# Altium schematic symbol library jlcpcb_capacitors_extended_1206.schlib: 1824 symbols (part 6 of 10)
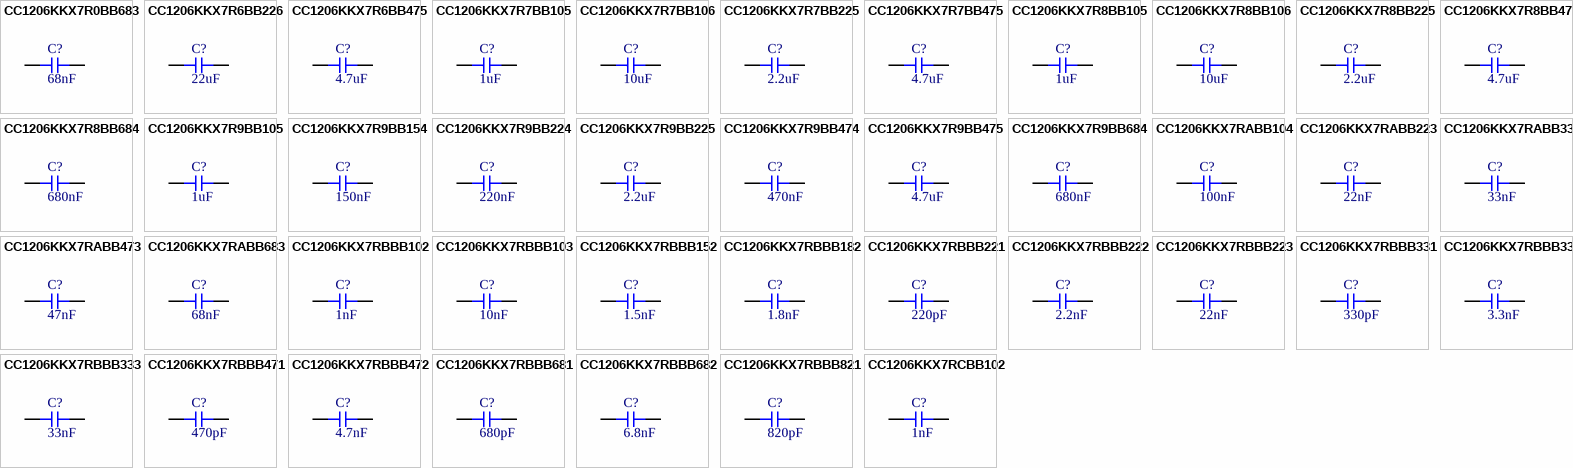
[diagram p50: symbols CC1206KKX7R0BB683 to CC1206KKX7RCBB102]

## CC1206KKX7RBBB223
designator C?  Capacitance: 22nF  (hidden comment: *)
Capacitor, Ceramic (MLCC), 22nF, ±10%, 500V, X7R, ±10%, SMD 1206; Manufacturer: YAGEO; Manufacturer Part Number: CC1206KKX7RBBB223
footprint CAP-1206 (1206 (3216M) Capacitor)
pins: 1, 2

## CC1206KKX7RBBB331
designator C?  Capacitance: 330pF  (hidden comment: *)
Capacitor, Ceramic (MLCC), 330pF, ±10%, 500V, X7R, ±10%, SMD 1206; Manufacturer: YAGEO; Manufacturer Part Number: CC1206KKX7RBBB331
footprint CAP-1206 (1206 (3216M) Capacitor)
pins: 1, 2

## CC1206KKX7RBBB332
designator C?  Capacitance: 3.3nF  (hidden comment: *)
Capacitor, Ceramic (MLCC), 3.3nF, ±10%, 500V, X7R, ±10%, SMD 1206; Manufacturer: YAGEO; Manufacturer Part Number: CC1206KKX7RBBB332
footprint CAP-1206 (1206 (3216M) Capacitor)
pins: 1, 2

## CC1206KKX7RBBB333
designator C?  Capacitance: 33nF  (hidden comment: *)
Capacitor, Ceramic (MLCC), 33nF, ±10%, 500V, X7R, ±10%, SMD 1206; Manufacturer: YAGEO; Manufacturer Part Number: CC1206KKX7RBBB333
footprint CAP-1206 (1206 (3216M) Capacitor)
pins: 1, 2

## CC1206KKX7RBBB471
designator C?  Capacitance: 470pF  (hidden comment: *)
Capacitor, Ceramic (MLCC), 470pF, ±10%, 500V, X7R, ±10%, SMD 1206; Manufacturer: YAGEO; Manufacturer Part Number: CC1206KKX7RBBB471
footprint CAP-1206 (1206 (3216M) Capacitor)
pins: 1, 2

## CC1206KKX7RBBB472
designator C?  Capacitance: 4.7nF  (hidden comment: *)
Capacitor, Ceramic (MLCC), 4.7nF, ±10%, 500V, X7R, ±10%, SMD 1206; Manufacturer: YAGEO; Manufacturer Part Number: CC1206KKX7RBBB472
footprint CAP-1206 (1206 (3216M) Capacitor)
pins: 1, 2

## CC1206KKX7RBBB681
designator C?  Capacitance: 680pF  (hidden comment: *)
Capacitor, Ceramic (MLCC), 680pF, ±10%, 500V, X7R, ±10%, SMD 1206; Manufacturer: YAGEO; Manufacturer Part Number: CC1206KKX7RBBB681
footprint CAP-1206 (1206 (3216M) Capacitor)
pins: 1, 2

## CC1206KKX7RBBB682
designator C?  Capacitance: 6.8nF  (hidden comment: *)
Capacitor, Ceramic (MLCC), 6.8nF, ±10%, 500V, X7R, ±10%, SMD 1206; Manufacturer: YAGEO; Manufacturer Part Number: CC1206KKX7RBBB682
footprint CAP-1206 (1206 (3216M) Capacitor)
pins: 1, 2

## CC1206KKX7RBBB821
designator C?  Capacitance: 820pF  (hidden comment: *)
Capacitor, Ceramic (MLCC), 820pF, ±10%, 500V, X7R, ±10%, SMD 1206; Manufacturer: YAGEO; Manufacturer Part Number: CC1206KKX7RBBB821
footprint CAP-1206 (1206 (3216M) Capacitor)
pins: 1, 2

## CC1206KKX7RCBB102
designator C?  Capacitance: 1nF  (hidden comment: *)
Capacitor, Ceramic (MLCC), 1nF, ±10%, 1kV, X7R, ±10%, SMD 1206; Manufacturer: YAGEO; Manufacturer Part Number: CC1206KKX7RCBB102
footprint CAP-1206 (1206 (3216M) Capacitor)
pins: 1, 2

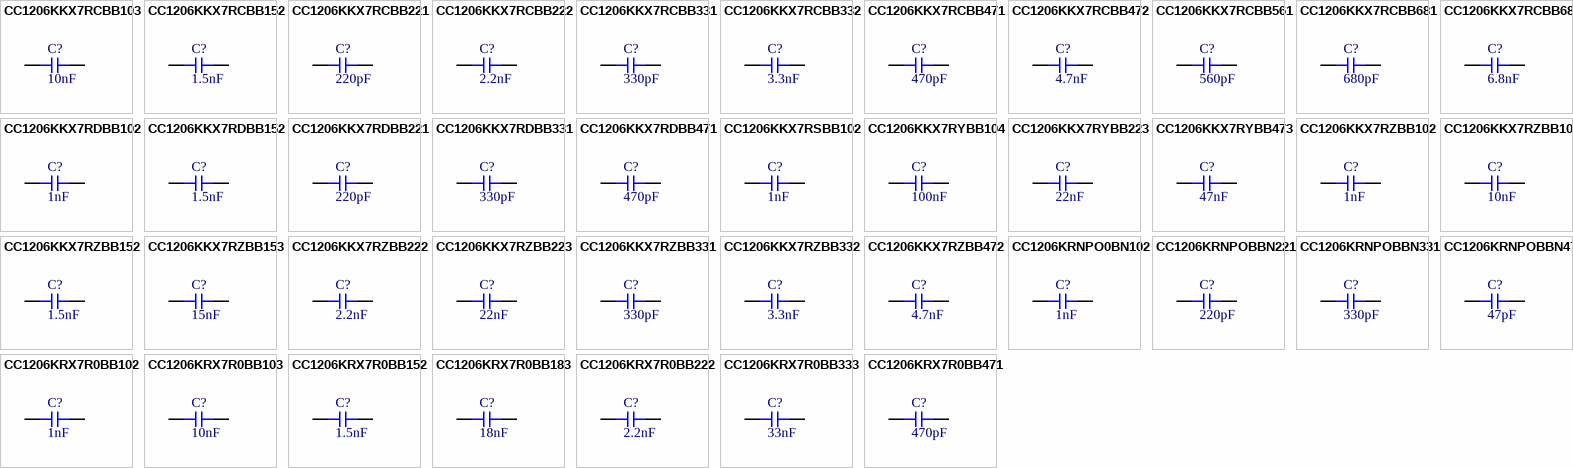
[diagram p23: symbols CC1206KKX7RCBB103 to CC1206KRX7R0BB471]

## CC1206KKX7RCBB103
designator C?  Capacitance: 10nF  (hidden comment: *)
Capacitor, Ceramic (MLCC), 10nF, ±10%, 1kV, X7R, ±10%, SMD 1206; Manufacturer: YAGEO; Manufacturer Part Number: CC1206KKX7RCBB103
footprint CAP-1206 (1206 (3216M) Capacitor)
pins: 1, 2

## CC1206KKX7RCBB152
designator C?  Capacitance: 1.5nF  (hidden comment: *)
Capacitor, Ceramic (MLCC), 1.5nF, ±10%, 1kV, X7R, ±10%, SMD 1206; Manufacturer: YAGEO; Manufacturer Part Number: CC1206KKX7RCBB152
footprint CAP-1206 (1206 (3216M) Capacitor)
pins: 1, 2

## CC1206KKX7RCBB221
designator C?  Capacitance: 220pF  (hidden comment: *)
Capacitor, Ceramic (MLCC), 220pF, ±10%, 1kV, X7R, ±10%, SMD 1206; Manufacturer: YAGEO; Manufacturer Part Number: CC1206KKX7RCBB221
footprint CAP-1206 (1206 (3216M) Capacitor)
pins: 1, 2

## CC1206KKX7RCBB222
designator C?  Capacitance: 2.2nF  (hidden comment: *)
Capacitor, Ceramic (MLCC), 2.2nF, ±10%, 1kV, X7R, ±10%, SMD 1206; Manufacturer: YAGEO; Manufacturer Part Number: CC1206KKX7RCBB222
footprint CAP-1206 (1206 (3216M) Capacitor)
pins: 1, 2

## CC1206KKX7RCBB331
designator C?  Capacitance: 330pF  (hidden comment: *)
Capacitor, Ceramic (MLCC), 330pF, ±10%, 1kV, X7R, ±10%, SMD 1206; Manufacturer: YAGEO; Manufacturer Part Number: CC1206KKX7RCBB331
footprint CAP-1206 (1206 (3216M) Capacitor)
pins: 1, 2

## CC1206KKX7RCBB332
designator C?  Capacitance: 3.3nF  (hidden comment: *)
Capacitor, Ceramic (MLCC), 3.3nF, ±10%, 1kV, X7R, ±10%, SMD 1206; Manufacturer: YAGEO; Manufacturer Part Number: CC1206KKX7RCBB332
footprint CAP-1206 (1206 (3216M) Capacitor)
pins: 1, 2

## CC1206KKX7RCBB471
designator C?  Capacitance: 470pF  (hidden comment: *)
Capacitor, Ceramic (MLCC), 470pF, ±10%, 1kV, X7R, ±10%, SMD 1206; Manufacturer: YAGEO; Manufacturer Part Number: CC1206KKX7RCBB471
footprint CAP-1206 (1206 (3216M) Capacitor)
pins: 1, 2

## CC1206KKX7RCBB472
designator C?  Capacitance: 4.7nF  (hidden comment: *)
Capacitor, Ceramic (MLCC), 4.7nF, ±10%, 1kV, X7R, ±10%, SMD 1206; Manufacturer: YAGEO; Manufacturer Part Number: CC1206KKX7RCBB472
footprint CAP-1206 (1206 (3216M) Capacitor)
pins: 1, 2

## CC1206KKX7RCBB561
designator C?  Capacitance: 560pF  (hidden comment: *)
Capacitor, Ceramic (MLCC), 560pF, ±10%, 1kV, X7R, ±10%, SMD 1206; Manufacturer: YAGEO; Manufacturer Part Number: CC1206KKX7RCBB561
footprint CAP-1206 (1206 (3216M) Capacitor)
pins: 1, 2

## CC1206KKX7RCBB681
designator C?  Capacitance: 680pF  (hidden comment: *)
Capacitor, Ceramic (MLCC), 680pF, ±10%, 1kV, X7R, ±10%, SMD 1206; Manufacturer: YAGEO; Manufacturer Part Number: CC1206KKX7RCBB681
footprint CAP-1206 (1206 (3216M) Capacitor)
pins: 1, 2

## CC1206KKX7RCBB682
designator C?  Capacitance: 6.8nF  (hidden comment: *)
Capacitor, Ceramic (MLCC), 6.8nF, ±10%, 1kV, X7R, ±10%, SMD 1206; Manufacturer: YAGEO; Manufacturer Part Number: CC1206KKX7RCBB682
footprint CAP-1206 (1206 (3216M) Capacitor)
pins: 1, 2

## CC1206KKX7RDBB102
designator C?  Capacitance: 1nF  (hidden comment: *)
Capacitor, Ceramic (MLCC), 1nF, ±10%, 2kV, X7R, ±10%, SMD 1206; Manufacturer: YAGEO; Manufacturer Part Number: CC1206KKX7RDBB102
footprint CAP-1206 (1206 (3216M) Capacitor)
pins: 1, 2

## CC1206KKX7RDBB152
designator C?  Capacitance: 1.5nF  (hidden comment: *)
Capacitor, Ceramic (MLCC), 1.5nF, ±10%, 2kV, X7R, ±10%, SMD 1206; Manufacturer: YAGEO; Manufacturer Part Number: CC1206KKX7RDBB152
footprint CAP-1206 (1206 (3216M) Capacitor)
pins: 1, 2

## CC1206KKX7RDBB221
designator C?  Capacitance: 220pF  (hidden comment: *)
Capacitor, Ceramic (MLCC), 220pF, ±10%, 2kV, X7R, ±10%, SMD 1206; Manufacturer: YAGEO; Manufacturer Part Number: CC1206KKX7RDBB221
footprint CAP-1206 (1206 (3216M) Capacitor)
pins: 1, 2

## CC1206KKX7RDBB331
designator C?  Capacitance: 330pF  (hidden comment: *)
Capacitor, Ceramic (MLCC), 330pF, ±10%, 2kV, X7R, ±10%, SMD 1206; Manufacturer: YAGEO; Manufacturer Part Number: CC1206KKX7RDBB331
footprint CAP-1206 (1206 (3216M) Capacitor)
pins: 1, 2

## CC1206KKX7RDBB471
designator C?  Capacitance: 470pF  (hidden comment: *)
Capacitor, Ceramic (MLCC), 470pF, ±10%, 2kV, X7R, ±10%, SMD 1206; Manufacturer: YAGEO; Manufacturer Part Number: CC1206KKX7RDBB471
footprint CAP-1206 (1206 (3216M) Capacitor)
pins: 1, 2

## CC1206KKX7RSBB102
designator C?  Capacitance: 1nF  (hidden comment: *)
Capacitor, Ceramic (MLCC), 1nF, ±10%, 2.5kV, X7R, ±10%, SMD 1206; Manufacturer: YAGEO; Manufacturer Part Number: CC1206KKX7RSBB102
footprint CAP-1206 (1206 (3216M) Capacitor)
pins: 1, 2

## CC1206KKX7RYBB104
designator C?  Capacitance: 100nF  (hidden comment: *)
Capacitor, Ceramic (MLCC), 100nF, ±10%, 250V, X7R, ±10%, SMD 1206; Manufacturer: YAGEO; Manufacturer Part Number: CC1206KKX7RYBB104
footprint CAP-1206 (1206 (3216M) Capacitor)
pins: 1, 2

## CC1206KKX7RYBB223
designator C?  Capacitance: 22nF  (hidden comment: *)
Capacitor, Ceramic (MLCC), 22nF, ±10%, 250V, X7R, ±10%, SMD 1206; Manufacturer: YAGEO; Manufacturer Part Number: CC1206KKX7RYBB223
footprint CAP-1206 (1206 (3216M) Capacitor)
pins: 1, 2

## CC1206KKX7RYBB473
designator C?  Capacitance: 47nF  (hidden comment: *)
Capacitor, Ceramic (MLCC), 47nF, ±10%, 250V, X7R, ±10%, SMD 1206; Manufacturer: YAGEO; Manufacturer Part Number: CC1206KKX7RYBB473
footprint CAP-1206 (1206 (3216M) Capacitor)
pins: 1, 2

## CC1206KKX7RZBB102
designator C?  Capacitance: 1nF  (hidden comment: *)
Capacitor, Ceramic (MLCC), 1nF, ±10%, 630V, X7R, ±10%, SMD 1206; Manufacturer: YAGEO; Manufacturer Part Number: CC1206KKX7RZBB102
footprint CAP-1206 (1206 (3216M) Capacitor)
pins: 1, 2

## CC1206KKX7RZBB103
designator C?  Capacitance: 10nF  (hidden comment: *)
Capacitor, Ceramic (MLCC), 10nF, ±10%, 630V, X7R, ±10%, SMD 1206; Manufacturer: YAGEO; Manufacturer Part Number: CC1206KKX7RZBB103
footprint CAP-1206 (1206 (3216M) Capacitor)
pins: 1, 2

## CC1206KKX7RZBB152
designator C?  Capacitance: 1.5nF  (hidden comment: *)
Capacitor, Ceramic (MLCC), 1.5nF, ±10%, 630V, X7R, ±10%, SMD 1206; Manufacturer: YAGEO; Manufacturer Part Number: CC1206KKX7RZBB152
footprint CAP-1206 (1206 (3216M) Capacitor)
pins: 1, 2

## CC1206KKX7RZBB153
designator C?  Capacitance: 15nF  (hidden comment: *)
Capacitor, Ceramic (MLCC), 15nF, ±10%, 630V, X7R, ±10%, SMD 1206; Manufacturer: YAGEO; Manufacturer Part Number: CC1206KKX7RZBB153
footprint CAP-1206 (1206 (3216M) Capacitor)
pins: 1, 2

## CC1206KKX7RZBB222
designator C?  Capacitance: 2.2nF  (hidden comment: *)
Capacitor, Ceramic (MLCC), 2.2nF, ±10%, 630V, X7R, ±10%, SMD 1206; Manufacturer: YAGEO; Manufacturer Part Number: CC1206KKX7RZBB222
footprint CAP-1206 (1206 (3216M) Capacitor)
pins: 1, 2

## CC1206KKX7RZBB223
designator C?  Capacitance: 22nF  (hidden comment: *)
Capacitor, Ceramic (MLCC), 22nF, ±10%, 630V, X7R, ±10%, SMD 1206; Manufacturer: YAGEO; Manufacturer Part Number: CC1206KKX7RZBB223
footprint CAP-1206 (1206 (3216M) Capacitor)
pins: 1, 2

## CC1206KKX7RZBB331
designator C?  Capacitance: 330pF  (hidden comment: *)
Capacitor, Ceramic (MLCC), 330pF, ±10%, 630V, X7R, ±10%, SMD 1206; Manufacturer: YAGEO; Manufacturer Part Number: CC1206KKX7RZBB331
footprint CAP-1206 (1206 (3216M) Capacitor)
pins: 1, 2

## CC1206KKX7RZBB332
designator C?  Capacitance: 3.3nF  (hidden comment: *)
Capacitor, Ceramic (MLCC), 3.3nF, ±10%, 630V, X7R, ±10%, SMD 1206; Manufacturer: YAGEO; Manufacturer Part Number: CC1206KKX7RZBB332
footprint CAP-1206 (1206 (3216M) Capacitor)
pins: 1, 2

## CC1206KKX7RZBB472
designator C?  Capacitance: 4.7nF  (hidden comment: *)
Capacitor, Ceramic (MLCC), 4.7nF, ±10%, 630V, X7R, ±10%, SMD 1206; Manufacturer: YAGEO; Manufacturer Part Number: CC1206KKX7RZBB472
footprint CAP-1206 (1206 (3216M) Capacitor)
pins: 1, 2

## CC1206KRNPO0BN102
designator C?  Capacitance: 1nF  (hidden comment: *)
Capacitor, Ceramic (MLCC), 1nF, ±10%, 100V, NP0, ±10%, SMD 1206; Manufacturer: YAGEO; Manufacturer Part Number: CC1206KRNPO0BN102
footprint CAP-1206 (1206 (3216M) Capacitor)
pins: 1, 2

## CC1206KRNPOBBN221
designator C?  Capacitance: 220pF  (hidden comment: *)
Capacitor, Ceramic (MLCC), 220pF, ±10%, 500V, NP0, ±10%, SMD 1206; Manufacturer: YAGEO; Manufacturer Part Number: CC1206KRNPOBBN221
footprint CAP-1206 (1206 (3216M) Capacitor)
pins: 1, 2

## CC1206KRNPOBBN331
designator C?  Capacitance: 330pF  (hidden comment: *)
Capacitor, Ceramic (MLCC), 330pF, ±10%, 500V, NP0, ±10%, SMD 1206; Manufacturer: YAGEO; Manufacturer Part Number: CC1206KRNPOBBN331
footprint CAP-1206 (1206 (3216M) Capacitor)
pins: 1, 2

## CC1206KRNPOBBN470
designator C?  Capacitance: 47pF  (hidden comment: *)
Capacitor, Ceramic (MLCC), 47pF, ±10%, 500V, NP0, ±10%, SMD 1206; Manufacturer: YAGEO; Manufacturer Part Number: CC1206KRNPOBBN470
footprint CAP-1206 (1206 (3216M) Capacitor)
pins: 1, 2

## CC1206KRX7R0BB102
designator C?  Capacitance: 1nF  (hidden comment: *)
Capacitor, Ceramic (MLCC), 1nF, ±10%, 100V, X7R, ±10%, SMD 1206; Manufacturer: YAGEO; Manufacturer Part Number: CC1206KRX7R0BB102
footprint CAP-1206 (1206 (3216M) Capacitor)
pins: 1, 2

## CC1206KRX7R0BB103
designator C?  Capacitance: 10nF  (hidden comment: *)
Capacitor, Ceramic (MLCC), 10nF, ±10%, 100V, X7R, ±10%, SMD 1206; Manufacturer: YAGEO; Manufacturer Part Number: CC1206KRX7R0BB103
footprint CAP-1206 (1206 (3216M) Capacitor)
pins: 1, 2

## CC1206KRX7R0BB152
designator C?  Capacitance: 1.5nF  (hidden comment: *)
Capacitor, Ceramic (MLCC), 1.5nF, ±10%, 100V, X7R, ±10%, SMD 1206; Manufacturer: YAGEO; Manufacturer Part Number: CC1206KRX7R0BB152
footprint CAP-1206 (1206 (3216M) Capacitor)
pins: 1, 2

## CC1206KRX7R0BB183
designator C?  Capacitance: 18nF  (hidden comment: *)
Capacitor, Ceramic (MLCC), 18nF, ±10%, 100V, X7R, ±10%, SMD 1206; Manufacturer: YAGEO; Manufacturer Part Number: CC1206KRX7R0BB183
footprint CAP-1206 (1206 (3216M) Capacitor)
pins: 1, 2

## CC1206KRX7R0BB222
designator C?  Capacitance: 2.2nF  (hidden comment: *)
Capacitor, Ceramic (MLCC), 2.2nF, ±10%, 100V, X7R, ±10%, SMD 1206; Manufacturer: YAGEO; Manufacturer Part Number: CC1206KRX7R0BB222
footprint CAP-1206 (1206 (3216M) Capacitor)
pins: 1, 2

## CC1206KRX7R0BB333
designator C?  Capacitance: 33nF  (hidden comment: *)
Capacitor, Ceramic (MLCC), 33nF, ±10%, 100V, X7R, ±10%, SMD 1206; Manufacturer: YAGEO; Manufacturer Part Number: CC1206KRX7R0BB333
footprint CAP-1206 (1206 (3216M) Capacitor)
pins: 1, 2

## CC1206KRX7R0BB471
designator C?  Capacitance: 470pF  (hidden comment: *)
Capacitor, Ceramic (MLCC), 470pF, ±10%, 100V, X7R, ±10%, SMD 1206; Manufacturer: YAGEO; Manufacturer Part Number: CC1206KRX7R0BB471
footprint CAP-1206 (1206 (3216M) Capacitor)
pins: 1, 2

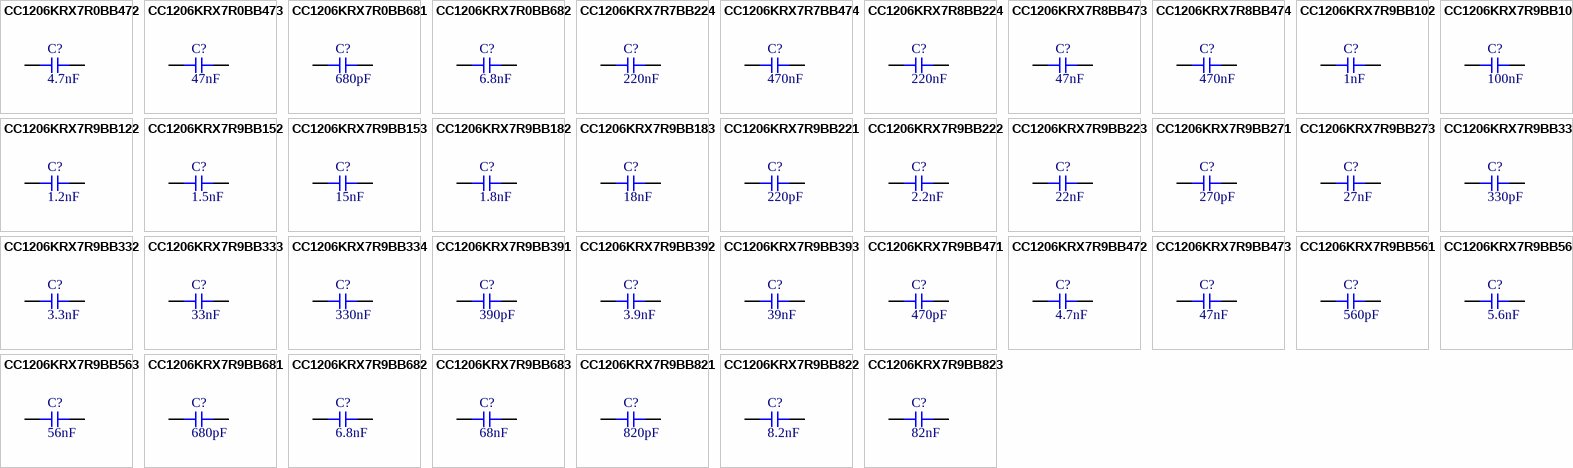
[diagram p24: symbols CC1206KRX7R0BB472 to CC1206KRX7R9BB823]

## CC1206KRX7R0BB472
designator C?  Capacitance: 4.7nF  (hidden comment: *)
Capacitor, Ceramic (MLCC), 4.7nF, ±10%, 100V, X7R, ±10%, SMD 1206; Manufacturer: YAGEO; Manufacturer Part Number: CC1206KRX7R0BB472
footprint CAP-1206 (1206 (3216M) Capacitor)
pins: 1, 2

## CC1206KRX7R0BB473
designator C?  Capacitance: 47nF  (hidden comment: *)
Capacitor, Ceramic (MLCC), 47nF, ±10%, 100V, X7R, ±10%, SMD 1206; Manufacturer: YAGEO; Manufacturer Part Number: CC1206KRX7R0BB473
footprint CAP-1206 (1206 (3216M) Capacitor)
pins: 1, 2

## CC1206KRX7R0BB681
designator C?  Capacitance: 680pF  (hidden comment: *)
Capacitor, Ceramic (MLCC), 680pF, ±10%, 100V, X7R, ±10%, SMD 1206; Manufacturer: YAGEO; Manufacturer Part Number: CC1206KRX7R0BB681
footprint CAP-1206 (1206 (3216M) Capacitor)
pins: 1, 2

## CC1206KRX7R0BB682
designator C?  Capacitance: 6.8nF  (hidden comment: *)
Capacitor, Ceramic (MLCC), 6.8nF, ±10%, 100V, X7R, ±10%, SMD 1206; Manufacturer: YAGEO; Manufacturer Part Number: CC1206KRX7R0BB682
footprint CAP-1206 (1206 (3216M) Capacitor)
pins: 1, 2

## CC1206KRX7R7BB224
designator C?  Capacitance: 220nF  (hidden comment: *)
Capacitor, Ceramic (MLCC), 220nF, ±10%, 16V, X7R, ±10%, SMD 1206; Manufacturer: YAGEO; Manufacturer Part Number: CC1206KRX7R7BB224
footprint CAP-1206 (1206 (3216M) Capacitor)
pins: 1, 2

## CC1206KRX7R7BB474
designator C?  Capacitance: 470nF  (hidden comment: *)
Capacitor, Ceramic (MLCC), 470nF, ±10%, 16V, X7R, ±10%, SMD 1206; Manufacturer: YAGEO; Manufacturer Part Number: CC1206KRX7R7BB474
footprint CAP-1206 (1206 (3216M) Capacitor)
pins: 1, 2

## CC1206KRX7R8BB224
designator C?  Capacitance: 220nF  (hidden comment: *)
Capacitor, Ceramic (MLCC), 220nF, ±10%, 25V, X7R, ±10%, SMD 1206; Manufacturer: YAGEO; Manufacturer Part Number: CC1206KRX7R8BB224
footprint CAP-1206 (1206 (3216M) Capacitor)
pins: 1, 2

## CC1206KRX7R8BB473
designator C?  Capacitance: 47nF  (hidden comment: *)
Capacitor, Ceramic (MLCC), 47nF, ±10%, 25V, X7R, ±10%, SMD 1206; Manufacturer: YAGEO; Manufacturer Part Number: CC1206KRX7R8BB473
footprint CAP-1206 (1206 (3216M) Capacitor)
pins: 1, 2

## CC1206KRX7R8BB474
designator C?  Capacitance: 470nF  (hidden comment: *)
Capacitor, Ceramic (MLCC), 470nF, ±10%, 25V, X7R, ±10%, SMD 1206; Manufacturer: YAGEO; Manufacturer Part Number: CC1206KRX7R8BB474
footprint CAP-1206 (1206 (3216M) Capacitor)
pins: 1, 2

## CC1206KRX7R9BB102
designator C?  Capacitance: 1nF  (hidden comment: *)
Capacitor, Ceramic (MLCC), 1nF, ±10%, 50V, X7R, ±10%, SMD 1206; Manufacturer: YAGEO; Manufacturer Part Number: CC1206KRX7R9BB102
footprint CAP-1206 (1206 (3216M) Capacitor)
pins: 1, 2

## CC1206KRX7R9BB104
designator C?  Capacitance: 100nF  (hidden comment: *)
Capacitor, Ceramic (MLCC), 100nF, ±10%, 50V, X7R, ±10%, SMD 1206; Manufacturer: YAGEO; Manufacturer Part Number: CC1206KRX7R9BB104
footprint CAP-1206 (1206 (3216M) Capacitor)
pins: 1, 2

## CC1206KRX7R9BB122
designator C?  Capacitance: 1.2nF  (hidden comment: *)
Capacitor, Ceramic (MLCC), 1.2nF, ±10%, 50V, X7R, ±10%, SMD 1206; Manufacturer: YAGEO; Manufacturer Part Number: CC1206KRX7R9BB122
footprint CAP-1206 (1206 (3216M) Capacitor)
pins: 1, 2

## CC1206KRX7R9BB152
designator C?  Capacitance: 1.5nF  (hidden comment: *)
Capacitor, Ceramic (MLCC), 1.5nF, ±10%, 50V, X7R, ±10%, SMD 1206; Manufacturer: YAGEO; Manufacturer Part Number: CC1206KRX7R9BB152
footprint CAP-1206 (1206 (3216M) Capacitor)
pins: 1, 2

## CC1206KRX7R9BB153
designator C?  Capacitance: 15nF  (hidden comment: *)
Capacitor, Ceramic (MLCC), 15nF, ±10%, 50V, X7R, ±10%, SMD 1206; Manufacturer: YAGEO; Manufacturer Part Number: CC1206KRX7R9BB153
footprint CAP-1206 (1206 (3216M) Capacitor)
pins: 1, 2

## CC1206KRX7R9BB182
designator C?  Capacitance: 1.8nF  (hidden comment: *)
Capacitor, Ceramic (MLCC), 1.8nF, ±10%, 50V, X7R, ±10%, SMD 1206; Manufacturer: YAGEO; Manufacturer Part Number: CC1206KRX7R9BB182
footprint CAP-1206 (1206 (3216M) Capacitor)
pins: 1, 2

## CC1206KRX7R9BB183
designator C?  Capacitance: 18nF  (hidden comment: *)
Capacitor, Ceramic (MLCC), 18nF, ±10%, 50V, X7R, ±10%, SMD 1206; Manufacturer: YAGEO; Manufacturer Part Number: CC1206KRX7R9BB183
footprint CAP-1206 (1206 (3216M) Capacitor)
pins: 1, 2

## CC1206KRX7R9BB221
designator C?  Capacitance: 220pF  (hidden comment: *)
Capacitor, Ceramic (MLCC), 220pF, ±10%, 50V, X7R, ±10%, SMD 1206; Manufacturer: YAGEO; Manufacturer Part Number: CC1206KRX7R9BB221
footprint CAP-1206 (1206 (3216M) Capacitor)
pins: 1, 2

## CC1206KRX7R9BB222
designator C?  Capacitance: 2.2nF  (hidden comment: *)
Capacitor, Ceramic (MLCC), 2.2nF, ±10%, 50V, X7R, ±10%, SMD 1206; Manufacturer: YAGEO; Manufacturer Part Number: CC1206KRX7R9BB222
footprint CAP-1206 (1206 (3216M) Capacitor)
pins: 1, 2

## CC1206KRX7R9BB223
designator C?  Capacitance: 22nF  (hidden comment: *)
Capacitor, Ceramic (MLCC), 22nF, ±10%, 50V, X7R, ±10%, SMD 1206; Manufacturer: YAGEO; Manufacturer Part Number: CC1206KRX7R9BB223
footprint CAP-1206 (1206 (3216M) Capacitor)
pins: 1, 2

## CC1206KRX7R9BB271
designator C?  Capacitance: 270pF  (hidden comment: *)
Capacitor, Ceramic (MLCC), 270pF, ±10%, 50V, X7R, ±10%, SMD 1206; Manufacturer: YAGEO; Manufacturer Part Number: CC1206KRX7R9BB271
footprint CAP-1206 (1206 (3216M) Capacitor)
pins: 1, 2

## CC1206KRX7R9BB273
designator C?  Capacitance: 27nF  (hidden comment: *)
Capacitor, Ceramic (MLCC), 27nF, ±10%, 50V, X7R, ±10%, SMD 1206; Manufacturer: YAGEO; Manufacturer Part Number: CC1206KRX7R9BB273
footprint CAP-1206 (1206 (3216M) Capacitor)
pins: 1, 2

## CC1206KRX7R9BB331
designator C?  Capacitance: 330pF  (hidden comment: *)
Capacitor, Ceramic (MLCC), 330pF, ±10%, 50V, X7R, ±10%, SMD 1206; Manufacturer: YAGEO; Manufacturer Part Number: CC1206KRX7R9BB331
footprint CAP-1206 (1206 (3216M) Capacitor)
pins: 1, 2

## CC1206KRX7R9BB332
designator C?  Capacitance: 3.3nF  (hidden comment: *)
Capacitor, Ceramic (MLCC), 3.3nF, ±10%, 50V, X7R, ±10%, SMD 1206; Manufacturer: YAGEO; Manufacturer Part Number: CC1206KRX7R9BB332
footprint CAP-1206 (1206 (3216M) Capacitor)
pins: 1, 2

## CC1206KRX7R9BB333
designator C?  Capacitance: 33nF  (hidden comment: *)
Capacitor, Ceramic (MLCC), 33nF, ±10%, 50V, X7R, ±10%, SMD 1206; Manufacturer: YAGEO; Manufacturer Part Number: CC1206KRX7R9BB333
footprint CAP-1206 (1206 (3216M) Capacitor)
pins: 1, 2

## CC1206KRX7R9BB334
designator C?  Capacitance: 330nF  (hidden comment: *)
Capacitor, Ceramic (MLCC), 330nF, ±10%, 50V, X7R, ±10%, SMD 1206; Manufacturer: YAGEO; Manufacturer Part Number: CC1206KRX7R9BB334
footprint CAP-1206 (1206 (3216M) Capacitor)
pins: 1, 2

## CC1206KRX7R9BB391
designator C?  Capacitance: 390pF  (hidden comment: *)
Capacitor, Ceramic (MLCC), 390pF, ±10%, 50V, X7R, ±10%, SMD 1206; Manufacturer: YAGEO; Manufacturer Part Number: CC1206KRX7R9BB391
footprint CAP-1206 (1206 (3216M) Capacitor)
pins: 1, 2

## CC1206KRX7R9BB392
designator C?  Capacitance: 3.9nF  (hidden comment: *)
Capacitor, Ceramic (MLCC), 3.9nF, ±10%, 50V, X7R, ±10%, SMD 1206; Manufacturer: YAGEO; Manufacturer Part Number: CC1206KRX7R9BB392
footprint CAP-1206 (1206 (3216M) Capacitor)
pins: 1, 2

## CC1206KRX7R9BB393
designator C?  Capacitance: 39nF  (hidden comment: *)
Capacitor, Ceramic (MLCC), 39nF, ±10%, 50V, X7R, ±10%, SMD 1206; Manufacturer: YAGEO; Manufacturer Part Number: CC1206KRX7R9BB393
footprint CAP-1206 (1206 (3216M) Capacitor)
pins: 1, 2

## CC1206KRX7R9BB471
designator C?  Capacitance: 470pF  (hidden comment: *)
Capacitor, Ceramic (MLCC), 470pF, ±10%, 50V, X7R, ±10%, SMD 1206; Manufacturer: YAGEO; Manufacturer Part Number: CC1206KRX7R9BB471
footprint CAP-1206 (1206 (3216M) Capacitor)
pins: 1, 2

## CC1206KRX7R9BB472
designator C?  Capacitance: 4.7nF  (hidden comment: *)
Capacitor, Ceramic (MLCC), 4.7nF, ±10%, 50V, X7R, ±10%, SMD 1206; Manufacturer: YAGEO; Manufacturer Part Number: CC1206KRX7R9BB472
footprint CAP-1206 (1206 (3216M) Capacitor)
pins: 1, 2

## CC1206KRX7R9BB473
designator C?  Capacitance: 47nF  (hidden comment: *)
Capacitor, Ceramic (MLCC), 47nF, ±10%, 50V, X7R, ±10%, SMD 1206; Manufacturer: YAGEO; Manufacturer Part Number: CC1206KRX7R9BB473
footprint CAP-1206 (1206 (3216M) Capacitor)
pins: 1, 2

## CC1206KRX7R9BB561
designator C?  Capacitance: 560pF  (hidden comment: *)
Capacitor, Ceramic (MLCC), 560pF, ±10%, 50V, X7R, ±10%, SMD 1206; Manufacturer: YAGEO; Manufacturer Part Number: CC1206KRX7R9BB561
footprint CAP-1206 (1206 (3216M) Capacitor)
pins: 1, 2

## CC1206KRX7R9BB562
designator C?  Capacitance: 5.6nF  (hidden comment: *)
Capacitor, Ceramic (MLCC), 5.6nF, ±10%, 50V, X7R, ±10%, SMD 1206; Manufacturer: YAGEO; Manufacturer Part Number: CC1206KRX7R9BB562
footprint CAP-1206 (1206 (3216M) Capacitor)
pins: 1, 2

## CC1206KRX7R9BB563
designator C?  Capacitance: 56nF  (hidden comment: *)
Capacitor, Ceramic (MLCC), 56nF, ±10%, 50V, X7R, ±10%, SMD 1206; Manufacturer: YAGEO; Manufacturer Part Number: CC1206KRX7R9BB563
footprint CAP-1206 (1206 (3216M) Capacitor)
pins: 1, 2

## CC1206KRX7R9BB681
designator C?  Capacitance: 680pF  (hidden comment: *)
Capacitor, Ceramic (MLCC), 680pF, ±10%, 50V, X7R, ±10%, SMD 1206; Manufacturer: YAGEO; Manufacturer Part Number: CC1206KRX7R9BB681
footprint CAP-1206 (1206 (3216M) Capacitor)
pins: 1, 2

## CC1206KRX7R9BB682
designator C?  Capacitance: 6.8nF  (hidden comment: *)
Capacitor, Ceramic (MLCC), 6.8nF, ±10%, 50V, X7R, ±10%, SMD 1206; Manufacturer: YAGEO; Manufacturer Part Number: CC1206KRX7R9BB682
footprint CAP-1206 (1206 (3216M) Capacitor)
pins: 1, 2

## CC1206KRX7R9BB683
designator C?  Capacitance: 68nF  (hidden comment: *)
Capacitor, Ceramic (MLCC), 68nF, ±10%, 50V, X7R, ±10%, SMD 1206; Manufacturer: YAGEO; Manufacturer Part Number: CC1206KRX7R9BB683
footprint CAP-1206 (1206 (3216M) Capacitor)
pins: 1, 2

## CC1206KRX7R9BB821
designator C?  Capacitance: 820pF  (hidden comment: *)
Capacitor, Ceramic (MLCC), 820pF, ±10%, 50V, X7R, ±10%, SMD 1206; Manufacturer: YAGEO; Manufacturer Part Number: CC1206KRX7R9BB821
footprint CAP-1206 (1206 (3216M) Capacitor)
pins: 1, 2

## CC1206KRX7R9BB822
designator C?  Capacitance: 8.2nF  (hidden comment: *)
Capacitor, Ceramic (MLCC), 8.2nF, ±10%, 50V, X7R, ±10%, SMD 1206; Manufacturer: YAGEO; Manufacturer Part Number: CC1206KRX7R9BB822
footprint CAP-1206 (1206 (3216M) Capacitor)
pins: 1, 2

## CC1206KRX7R9BB823
designator C?  Capacitance: 82nF  (hidden comment: *)
Capacitor, Ceramic (MLCC), 82nF, ±10%, 50V, X7R, ±10%, SMD 1206; Manufacturer: YAGEO; Manufacturer Part Number: CC1206KRX7R9BB823
footprint CAP-1206 (1206 (3216M) Capacitor)
pins: 1, 2

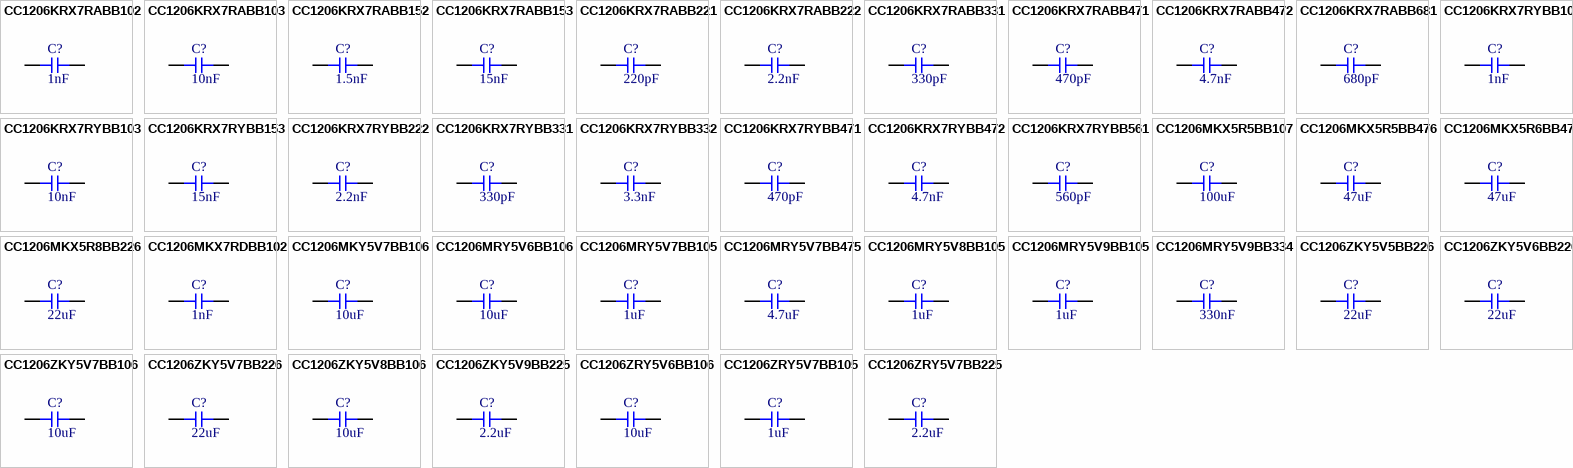
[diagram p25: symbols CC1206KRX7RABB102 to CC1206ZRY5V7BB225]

## CC1206KRX7RABB102
designator C?  Capacitance: 1nF  (hidden comment: *)
Capacitor, Ceramic (MLCC), 1nF, ±10%, 200V, X7R, ±10%, SMD 1206; Manufacturer: YAGEO; Manufacturer Part Number: CC1206KRX7RABB102
footprint CAP-1206 (1206 (3216M) Capacitor)
pins: 1, 2

## CC1206KRX7RABB103
designator C?  Capacitance: 10nF  (hidden comment: *)
Capacitor, Ceramic (MLCC), 10nF, ±10%, 200V, X7R, ±10%, SMD 1206; Manufacturer: YAGEO; Manufacturer Part Number: CC1206KRX7RABB103
footprint CAP-1206 (1206 (3216M) Capacitor)
pins: 1, 2

## CC1206KRX7RABB152
designator C?  Capacitance: 1.5nF  (hidden comment: *)
Capacitor, Ceramic (MLCC), 1.5nF, ±10%, 200V, X7R, ±10%, SMD 1206; Manufacturer: YAGEO; Manufacturer Part Number: CC1206KRX7RABB152
footprint CAP-1206 (1206 (3216M) Capacitor)
pins: 1, 2

## CC1206KRX7RABB153
designator C?  Capacitance: 15nF  (hidden comment: *)
Capacitor, Ceramic (MLCC), 15nF, ±10%, 200V, X7R, ±10%, SMD 1206; Manufacturer: YAGEO; Manufacturer Part Number: CC1206KRX7RABB153
footprint CAP-1206 (1206 (3216M) Capacitor)
pins: 1, 2

## CC1206KRX7RABB221
designator C?  Capacitance: 220pF  (hidden comment: *)
Capacitor, Ceramic (MLCC), 220pF, ±10%, 200V, X7R, ±10%, SMD 1206; Manufacturer: YAGEO; Manufacturer Part Number: CC1206KRX7RABB221
footprint CAP-1206 (1206 (3216M) Capacitor)
pins: 1, 2

## CC1206KRX7RABB222
designator C?  Capacitance: 2.2nF  (hidden comment: *)
Capacitor, Ceramic (MLCC), 2.2nF, ±10%, 200V, X7R, ±10%, SMD 1206; Manufacturer: YAGEO; Manufacturer Part Number: CC1206KRX7RABB222
footprint CAP-1206 (1206 (3216M) Capacitor)
pins: 1, 2

## CC1206KRX7RABB331
designator C?  Capacitance: 330pF  (hidden comment: *)
Capacitor, Ceramic (MLCC), 330pF, ±10%, 200V, X7R, ±10%, SMD 1206; Manufacturer: YAGEO; Manufacturer Part Number: CC1206KRX7RABB331
footprint CAP-1206 (1206 (3216M) Capacitor)
pins: 1, 2

## CC1206KRX7RABB471
designator C?  Capacitance: 470pF  (hidden comment: *)
Capacitor, Ceramic (MLCC), 470pF, ±10%, 200V, X7R, ±10%, SMD 1206; Manufacturer: YAGEO; Manufacturer Part Number: CC1206KRX7RABB471
footprint CAP-1206 (1206 (3216M) Capacitor)
pins: 1, 2

## CC1206KRX7RABB472
designator C?  Capacitance: 4.7nF  (hidden comment: *)
Capacitor, Ceramic (MLCC), 4.7nF, ±10%, 200V, X7R, ±10%, SMD 1206; Manufacturer: YAGEO; Manufacturer Part Number: CC1206KRX7RABB472
footprint CAP-1206 (1206 (3216M) Capacitor)
pins: 1, 2

## CC1206KRX7RABB681
designator C?  Capacitance: 680pF  (hidden comment: *)
Capacitor, Ceramic (MLCC), 680pF, ±10%, 200V, X7R, ±10%, SMD 1206; Manufacturer: YAGEO; Manufacturer Part Number: CC1206KRX7RABB681
footprint CAP-1206 (1206 (3216M) Capacitor)
pins: 1, 2

## CC1206KRX7RYBB102
designator C?  Capacitance: 1nF  (hidden comment: *)
Capacitor, Ceramic (MLCC), 1nF, ±10%, 250V, X7R, ±10%, SMD 1206; Manufacturer: YAGEO; Manufacturer Part Number: CC1206KRX7RYBB102
footprint CAP-1206 (1206 (3216M) Capacitor)
pins: 1, 2

## CC1206KRX7RYBB103
designator C?  Capacitance: 10nF  (hidden comment: *)
Capacitor, Ceramic (MLCC), 10nF, ±10%, 250V, X7R, ±10%, SMD 1206; Manufacturer: YAGEO; Manufacturer Part Number: CC1206KRX7RYBB103
footprint CAP-1206 (1206 (3216M) Capacitor)
pins: 1, 2

## CC1206KRX7RYBB153
designator C?  Capacitance: 15nF  (hidden comment: *)
Capacitor, Ceramic (MLCC), 15nF, ±10%, 250V, X7R, ±10%, SMD 1206; Manufacturer: YAGEO; Manufacturer Part Number: CC1206KRX7RYBB153
footprint CAP-1206 (1206 (3216M) Capacitor)
pins: 1, 2

## CC1206KRX7RYBB222
designator C?  Capacitance: 2.2nF  (hidden comment: *)
Capacitor, Ceramic (MLCC), 2.2nF, ±10%, 250V, X7R, ±10%, SMD 1206; Manufacturer: YAGEO; Manufacturer Part Number: CC1206KRX7RYBB222
footprint CAP-1206 (1206 (3216M) Capacitor)
pins: 1, 2

## CC1206KRX7RYBB331
designator C?  Capacitance: 330pF  (hidden comment: *)
Capacitor, Ceramic (MLCC), 330pF, ±10%, 250V, X7R, ±10%, SMD 1206; Manufacturer: YAGEO; Manufacturer Part Number: CC1206KRX7RYBB331
footprint CAP-1206 (1206 (3216M) Capacitor)
pins: 1, 2

## CC1206KRX7RYBB332
designator C?  Capacitance: 3.3nF  (hidden comment: *)
Capacitor, Ceramic (MLCC), 3.3nF, ±10%, 250V, X7R, ±10%, SMD 1206; Manufacturer: YAGEO; Manufacturer Part Number: CC1206KRX7RYBB332
footprint CAP-1206 (1206 (3216M) Capacitor)
pins: 1, 2

## CC1206KRX7RYBB471
designator C?  Capacitance: 470pF  (hidden comment: *)
Capacitor, Ceramic (MLCC), 470pF, ±10%, 250V, X7R, ±10%, SMD 1206; Manufacturer: YAGEO; Manufacturer Part Number: CC1206KRX7RYBB471
footprint CAP-1206 (1206 (3216M) Capacitor)
pins: 1, 2

## CC1206KRX7RYBB472
designator C?  Capacitance: 4.7nF  (hidden comment: *)
Capacitor, Ceramic (MLCC), 4.7nF, ±10%, 250V, X7R, ±10%, SMD 1206; Manufacturer: YAGEO; Manufacturer Part Number: CC1206KRX7RYBB472
footprint CAP-1206 (1206 (3216M) Capacitor)
pins: 1, 2

## CC1206KRX7RYBB561
designator C?  Capacitance: 560pF  (hidden comment: *)
Capacitor, Ceramic (MLCC), 560pF, ±10%, 250V, X7R, ±10%, SMD 1206; Manufacturer: YAGEO; Manufacturer Part Number: CC1206KRX7RYBB561
footprint CAP-1206 (1206 (3216M) Capacitor)
pins: 1, 2

## CC1206MKX5R5BB107
designator C?  Capacitance: 100uF  (hidden comment: *)
Capacitor, Ceramic (MLCC), 100uF, ±20%, 6.3V, X5R, ±20%, SMD 1206; Manufacturer: YAGEO; Manufacturer Part Number: CC1206MKX5R5BB107
footprint CAP-1206 (1206 (3216M) Capacitor)
pins: 1, 2

## CC1206MKX5R5BB476
designator C?  Capacitance: 47uF  (hidden comment: *)
Capacitor, Ceramic (MLCC), 47uF, ±20%, 6.3V, X5R, ±20%, SMD 1206; Manufacturer: YAGEO; Manufacturer Part Number: CC1206MKX5R5BB476
footprint CAP-1206 (1206 (3216M) Capacitor)
pins: 1, 2

## CC1206MKX5R6BB476
designator C?  Capacitance: 47uF  (hidden comment: *)
Capacitor, Ceramic (MLCC), 47uF, ±20%, 10V, X5R, ±20%, SMD 1206; Manufacturer: YAGEO; Manufacturer Part Number: CC1206MKX5R6BB476
footprint CAP-1206 (1206 (3216M) Capacitor)
pins: 1, 2

## CC1206MKX5R8BB226
designator C?  Capacitance: 22uF  (hidden comment: *)
Capacitor, Ceramic (MLCC), 22uF, ±20%, 25V, X5R, ±20%, SMD 1206; Manufacturer: YAGEO; Manufacturer Part Number: CC1206MKX5R8BB226
footprint CAP-1206 (1206 (3216M) Capacitor)
pins: 1, 2

## CC1206MKX7RDBB102
designator C?  Capacitance: 1nF  (hidden comment: *)
Capacitor, Ceramic (MLCC), 1nF, ±20%, 2kV, X7R, ±20%, SMD 1206; Manufacturer: YAGEO; Manufacturer Part Number: CC1206MKX7RDBB102
footprint CAP-1206 (1206 (3216M) Capacitor)
pins: 1, 2

## CC1206MKY5V7BB106
designator C?  Capacitance: 10uF  (hidden comment: *)
Capacitor, Ceramic (MLCC), 10uF, ±20%, 16V, Y5V, ±20%, SMD 1206; Manufacturer: YAGEO; Manufacturer Part Number: CC1206MKY5V7BB106
footprint CAP-1206 (1206 (3216M) Capacitor)
pins: 1, 2

## CC1206MRY5V6BB106
designator C?  Capacitance: 10uF  (hidden comment: *)
Capacitor, Ceramic (MLCC), 10uF, ±20%, 10V, Y5V, ±20%, SMD 1206; Manufacturer: YAGEO; Manufacturer Part Number: CC1206MRY5V6BB106
footprint CAP-1206 (1206 (3216M) Capacitor)
pins: 1, 2

## CC1206MRY5V7BB105
designator C?  Capacitance: 1uF  (hidden comment: *)
Capacitor, Ceramic (MLCC), 1uF, ±20%, 16V, Y5V, ±20%, SMD 1206; Manufacturer: YAGEO; Manufacturer Part Number: CC1206MRY5V7BB105
footprint CAP-1206 (1206 (3216M) Capacitor)
pins: 1, 2

## CC1206MRY5V7BB475
designator C?  Capacitance: 4.7uF  (hidden comment: *)
Capacitor, Ceramic (MLCC), 4.7uF, ±20%, 16V, Y5V, ±20%, SMD 1206; Manufacturer: YAGEO; Manufacturer Part Number: CC1206MRY5V7BB475
footprint CAP-1206 (1206 (3216M) Capacitor)
pins: 1, 2

## CC1206MRY5V8BB105
designator C?  Capacitance: 1uF  (hidden comment: *)
Capacitor, Ceramic (MLCC), 1uF, ±20%, 25V, Y5V, ±20%, SMD 1206; Manufacturer: YAGEO; Manufacturer Part Number: CC1206MRY5V8BB105
footprint CAP-1206 (1206 (3216M) Capacitor)
pins: 1, 2

## CC1206MRY5V9BB105
designator C?  Capacitance: 1uF  (hidden comment: *)
Capacitor, Ceramic (MLCC), 1uF, ±20%, 50V, Y5V, ±20%, SMD 1206; Manufacturer: YAGEO; Manufacturer Part Number: CC1206MRY5V9BB105
footprint CAP-1206 (1206 (3216M) Capacitor)
pins: 1, 2

## CC1206MRY5V9BB334
designator C?  Capacitance: 330nF  (hidden comment: *)
Capacitor, Ceramic (MLCC), 330nF, ±20%, 50V, Y5V, ±20%, SMD 1206; Manufacturer: YAGEO; Manufacturer Part Number: CC1206MRY5V9BB334
footprint CAP-1206 (1206 (3216M) Capacitor)
pins: 1, 2

## CC1206ZKY5V5BB226
designator C?  Capacitance: 22uF  (hidden comment: *)
Capacitor, Ceramic (MLCC), 22uF, 6.3V, Y5V, SMD 1206; Manufacturer: YAGEO; Manufacturer Part Number: CC1206ZKY5V5BB226; Temperature Rating: -20%~+80%
footprint CAP-1206 (1206 (3216M) Capacitor)
pins: 1, 2

## CC1206ZKY5V6BB226
designator C?  Capacitance: 22uF  (hidden comment: *)
Capacitor, Ceramic (MLCC), 22uF, 10V, Y5V, SMD 1206; Manufacturer: YAGEO; Manufacturer Part Number: CC1206ZKY5V6BB226; Temperature Rating: -20%~+80%
footprint CAP-1206 (1206 (3216M) Capacitor)
pins: 1, 2

## CC1206ZKY5V7BB106
designator C?  Capacitance: 10uF  (hidden comment: *)
Capacitor, Ceramic (MLCC), 10uF, 16V, Y5V, SMD 1206; Manufacturer: YAGEO; Manufacturer Part Number: CC1206ZKY5V7BB106; Temperature Rating: -20%~+80%
footprint CAP-1206 (1206 (3216M) Capacitor)
pins: 1, 2

## CC1206ZKY5V7BB226
designator C?  Capacitance: 22uF  (hidden comment: *)
Capacitor, Ceramic (MLCC), 22uF, 16V, Y5V, SMD 1206; Manufacturer: YAGEO; Manufacturer Part Number: CC1206ZKY5V7BB226; Temperature Rating: -20%~+80%
footprint CAP-1206 (1206 (3216M) Capacitor)
pins: 1, 2

## CC1206ZKY5V8BB106
designator C?  Capacitance: 10uF  (hidden comment: *)
Capacitor, Ceramic (MLCC), 10uF, 25V, Y5V, SMD 1206; Manufacturer: YAGEO; Manufacturer Part Number: CC1206ZKY5V8BB106; Temperature Rating: -20%~+80%
footprint CAP-1206 (1206 (3216M) Capacitor)
pins: 1, 2

## CC1206ZKY5V9BB225
designator C?  Capacitance: 2.2uF  (hidden comment: *)
Capacitor, Ceramic (MLCC), 2.2uF, 50V, Y5V, SMD 1206; Manufacturer: YAGEO; Manufacturer Part Number: CC1206ZKY5V9BB225; Temperature Rating: -20%~+80%
footprint CAP-1206 (1206 (3216M) Capacitor)
pins: 1, 2

## CC1206ZRY5V6BB106
designator C?  Capacitance: 10uF  (hidden comment: *)
Capacitor, Ceramic (MLCC), 10uF, 10V, Y5V, SMD 1206; Manufacturer: YAGEO; Manufacturer Part Number: CC1206ZRY5V6BB106; Temperature Rating: -20%~+80%
footprint CAP-1206 (1206 (3216M) Capacitor)
pins: 1, 2

## CC1206ZRY5V7BB105
designator C?  Capacitance: 1uF  (hidden comment: *)
Capacitor, Ceramic (MLCC), 1uF, 16V, Y5V, SMD 1206; Manufacturer: YAGEO; Manufacturer Part Number: CC1206ZRY5V7BB105; Temperature Rating: -20%~+80%
footprint CAP-1206 (1206 (3216M) Capacitor)
pins: 1, 2

## CC1206ZRY5V7BB225
designator C?  Capacitance: 2.2uF  (hidden comment: *)
Capacitor, Ceramic (MLCC), 2.2uF, 16V, Y5V, SMD 1206; Manufacturer: YAGEO; Manufacturer Part Number: CC1206ZRY5V7BB225; Temperature Rating: -20%~+80%
footprint CAP-1206 (1206 (3216M) Capacitor)
pins: 1, 2

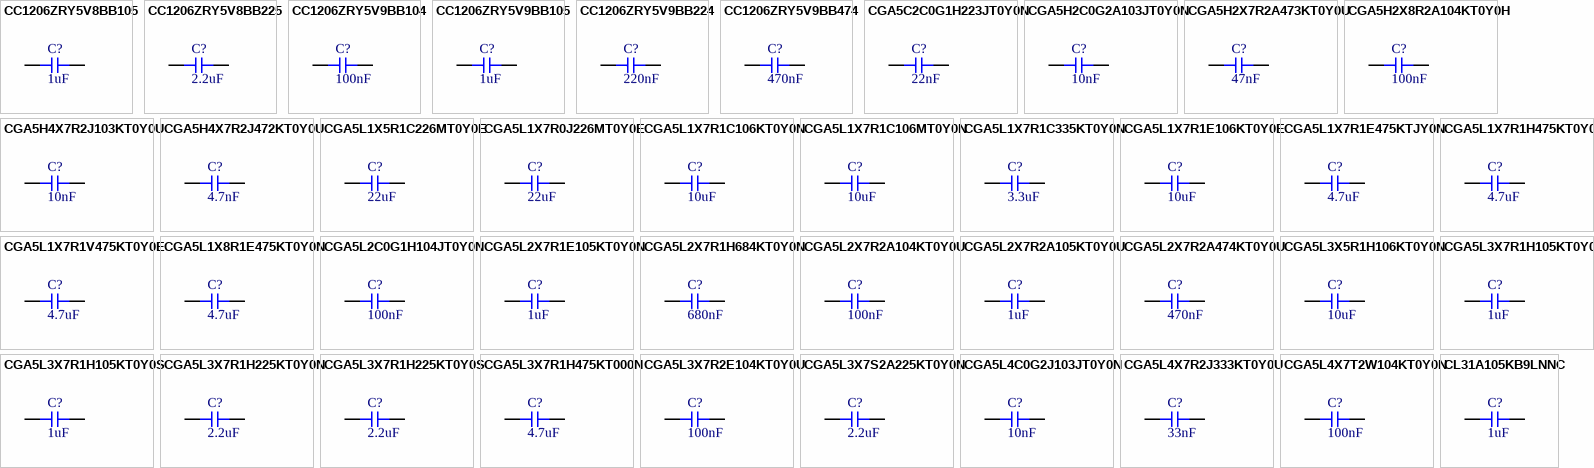
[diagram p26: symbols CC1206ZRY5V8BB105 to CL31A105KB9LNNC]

## CC1206ZRY5V8BB105
designator C?  Capacitance: 1uF  (hidden comment: *)
Capacitor, Ceramic (MLCC), 1uF, 25V, Y5V, SMD 1206; Manufacturer: YAGEO; Manufacturer Part Number: CC1206ZRY5V8BB105; Temperature Rating: -20%~+80%
footprint CAP-1206 (1206 (3216M) Capacitor)
pins: 1, 2

## CC1206ZRY5V8BB225
designator C?  Capacitance: 2.2uF  (hidden comment: *)
Capacitor, Ceramic (MLCC), 2.2uF, 25V, Y5V, SMD 1206; Manufacturer: YAGEO; Manufacturer Part Number: CC1206ZRY5V8BB225; Temperature Rating: -20%~+80%
footprint CAP-1206 (1206 (3216M) Capacitor)
pins: 1, 2

## CC1206ZRY5V9BB104
designator C?  Capacitance: 100nF  (hidden comment: *)
Capacitor, Ceramic (MLCC), 100nF, 50V, Y5V, SMD 1206; Manufacturer: YAGEO; Manufacturer Part Number: CC1206ZRY5V9BB104; Temperature Rating: -20%~+80%
footprint CAP-1206 (1206 (3216M) Capacitor)
pins: 1, 2

## CC1206ZRY5V9BB105
designator C?  Capacitance: 1uF  (hidden comment: *)
Capacitor, Ceramic (MLCC), 1uF, 50V, Y5V, SMD 1206; Manufacturer: YAGEO; Manufacturer Part Number: CC1206ZRY5V9BB105; Temperature Rating: -20%~+80%
footprint CAP-1206 (1206 (3216M) Capacitor)
pins: 1, 2

## CC1206ZRY5V9BB224
designator C?  Capacitance: 220nF  (hidden comment: *)
Capacitor, Ceramic (MLCC), 220nF, 50V, Y5V, SMD 1206; Manufacturer: YAGEO; Manufacturer Part Number: CC1206ZRY5V9BB224; Temperature Rating: -20%~+80%
footprint CAP-1206 (1206 (3216M) Capacitor)
pins: 1, 2

## CC1206ZRY5V9BB474
designator C?  Capacitance: 470nF  (hidden comment: *)
Capacitor, Ceramic (MLCC), 470nF, 50V, Y5V, SMD 1206; Manufacturer: YAGEO; Manufacturer Part Number: CC1206ZRY5V9BB474; Temperature Rating: -20%~+80%
footprint CAP-1206 (1206 (3216M) Capacitor)
pins: 1, 2

## CGA5C2C0G1H223JT0Y0N
designator C?  Capacitance: 22nF  (hidden comment: *)
Capacitor, Ceramic (MLCC), 22nF, ±5%, 50V, C0G, ±5%, SMD 1206; Manufacturer: TDK; Manufacturer Part Number: CGA5C2C0G1H223JT0Y0N
footprint CAP-1206 (1206 (3216M) Capacitor)
pins: 1, 2

## CGA5H2C0G2A103JT0Y0N
designator C?  Capacitance: 10nF  (hidden comment: *)
Capacitor, Ceramic (MLCC), 10nF, ±5%, 100V, C0G, ±5%, SMD 1206; Manufacturer: TDK; Manufacturer Part Number: CGA5H2C0G2A103JT0Y0N
footprint CAP-1206 (1206 (3216M) Capacitor)
pins: 1, 2

## CGA5H2X7R2A473KT0Y0U
designator C?  Capacitance: 47nF  (hidden comment: *)
Capacitor, Ceramic (MLCC), 47nF, ±10%, 100V, X7R, ±10%, SMD 1206; Manufacturer: TDK; Manufacturer Part Number: CGA5H2X7R2A473KT0Y0U
footprint CAP-1206 (1206 (3216M) Capacitor)
pins: 1, 2

## CGA5H2X8R2A104KT0Y0H
designator C?  Capacitance: 100nF  (hidden comment: *)
Capacitor, Ceramic (MLCC), 100nF, ±10%, 100V, X8R, ±10%, SMD 1206; Manufacturer: TDK; Manufacturer Part Number: CGA5H2X8R2A104KT0Y0H
footprint CAP-1206 (1206 (3216M) Capacitor)
pins: 1, 2

## CGA5H4X7R2J103KT0Y0U
designator C?  Capacitance: 10nF  (hidden comment: *)
Capacitor, Ceramic (MLCC), 10nF, ±10%, 630V, X7R, ±10%, SMD 1206; Manufacturer: TDK; Manufacturer Part Number: CGA5H4X7R2J103KT0Y0U
footprint CAP-1206 (1206 (3216M) Capacitor)
pins: 1, 2

## CGA5H4X7R2J472KT0Y0U
designator C?  Capacitance: 4.7nF  (hidden comment: *)
Capacitor, Ceramic (MLCC), 4.7nF, ±10%, 630V, X7R, ±10%, SMD 1206; Manufacturer: TDK; Manufacturer Part Number: CGA5H4X7R2J472KT0Y0U
footprint CAP-1206 (1206 (3216M) Capacitor)
pins: 1, 2

## CGA5L1X5R1C226MT0Y0E
designator C?  Capacitance: 22uF  (hidden comment: *)
Capacitor, Ceramic (MLCC), 22uF, ±20%, 16V, X5R, ±20%, SMD 1206; Manufacturer: TDK; Manufacturer Part Number: CGA5L1X5R1C226MT0Y0E
footprint CAP-1206 (1206 (3216M) Capacitor)
pins: 1, 2

## CGA5L1X7R0J226MT0Y0E
designator C?  Capacitance: 22uF  (hidden comment: *)
Capacitor, Ceramic (MLCC), 22uF, ±20%, 6.3V, X7R, ±20%, SMD 1206; Manufacturer: TDK; Manufacturer Part Number: CGA5L1X7R0J226MT0Y0E
footprint CAP-1206 (1206 (3216M) Capacitor)
pins: 1, 2

## CGA5L1X7R1C106KT0Y0N
designator C?  Capacitance: 10uF  (hidden comment: *)
Capacitor, Ceramic (MLCC), 10uF, ±10%, 16V, X7R, ±10%, SMD 1206; Manufacturer: TDK; Manufacturer Part Number: CGA5L1X7R1C106KT0Y0N
footprint CAP-1206 (1206 (3216M) Capacitor)
pins: 1, 2

## CGA5L1X7R1C106MT0Y0N
designator C?  Capacitance: 10uF  (hidden comment: *)
Capacitor, Ceramic (MLCC), 10uF, ±20%, 16V, X7R, ±20%, SMD 1206; Manufacturer: TDK; Manufacturer Part Number: CGA5L1X7R1C106MT0Y0N
footprint CAP-1206 (1206 (3216M) Capacitor)
pins: 1, 2

## CGA5L1X7R1C335KT0Y0N
designator C?  Capacitance: 3.3uF  (hidden comment: *)
Capacitor, Ceramic (MLCC), 3.3uF, ±10%, 16V, X7R, ±10%, SMD 1206; Manufacturer: TDK; Manufacturer Part Number: CGA5L1X7R1C335KT0Y0N
footprint CAP-1206 (1206 (3216M) Capacitor)
pins: 1, 2

## CGA5L1X7R1E106KT0Y0E
designator C?  Capacitance: 10uF  (hidden comment: *)
Capacitor, Ceramic (MLCC), 10uF, ±10%, 25V, X7R, ±10%, SMD 1206; Manufacturer: TDK; Manufacturer Part Number: CGA5L1X7R1E106KT0Y0E
footprint CAP-1206 (1206 (3216M) Capacitor)
pins: 1, 2

## CGA5L1X7R1E475KTJY0N
designator C?  Capacitance: 4.7uF  (hidden comment: *)
Capacitor, Ceramic (MLCC), 4.7uF, ±10%, 25V, X7R, ±10%, SMD 1206; Manufacturer: TDK; Manufacturer Part Number: CGA5L1X7R1E475KTJY0N
footprint CAP-1206 (1206 (3216M) Capacitor)
pins: 1, 2

## CGA5L1X7R1H475KT0Y0S
designator C?  Capacitance: 4.7uF  (hidden comment: *)
Capacitor, Ceramic (MLCC), 4.7uF, ±10%, 50V, X7R, ±10%, SMD 1206; Manufacturer: TDK; Manufacturer Part Number: CGA5L1X7R1H475KT0Y0S
footprint CAP-1206 (1206 (3216M) Capacitor)
pins: 1, 2

## CGA5L1X7R1V475KT0Y0E
designator C?  Capacitance: 4.7uF  (hidden comment: *)
Capacitor, Ceramic (MLCC), 4.7uF, ±10%, 35V, X7R, ±10%, SMD 1206; Manufacturer: TDK; Manufacturer Part Number: CGA5L1X7R1V475KT0Y0E
footprint CAP-1206 (1206 (3216M) Capacitor)
pins: 1, 2

## CGA5L1X8R1E475KT0Y0N
designator C?  Capacitance: 4.7uF  (hidden comment: *)
Capacitor, Ceramic (MLCC), 4.7uF, ±10%, 25V, X8R, ±10%, SMD 1206; Manufacturer: TDK; Manufacturer Part Number: CGA5L1X8R1E475KT0Y0N
footprint CAP-1206 (1206 (3216M) Capacitor)
pins: 1, 2

## CGA5L2C0G1H104JT0Y0N
designator C?  Capacitance: 100nF  (hidden comment: *)
Capacitor, Ceramic (MLCC), 100nF, ±5%, 50V, C0G, ±5%, SMD 1206; Manufacturer: TDK; Manufacturer Part Number: CGA5L2C0G1H104JT0Y0N
footprint CAP-1206 (1206 (3216M) Capacitor)
pins: 1, 2

## CGA5L2X7R1E105KT0Y0N
designator C?  Capacitance: 1uF  (hidden comment: *)
Capacitor, Ceramic (MLCC), 1uF, ±10%, 25V, X7R, ±10%, SMD 1206; Manufacturer: TDK; Manufacturer Part Number: CGA5L2X7R1E105KT0Y0N
footprint CAP-1206 (1206 (3216M) Capacitor)
pins: 1, 2

## CGA5L2X7R1H684KT0Y0N
designator C?  Capacitance: 680nF  (hidden comment: *)
Capacitor, Ceramic (MLCC), 680nF, ±10%, 50V, X7R, ±10%, SMD 1206; Manufacturer: TDK; Manufacturer Part Number: CGA5L2X7R1H684KT0Y0N
footprint CAP-1206 (1206 (3216M) Capacitor)
pins: 1, 2

## CGA5L2X7R2A104KT0Y0U
designator C?  Capacitance: 100nF  (hidden comment: *)
Capacitor, Ceramic (MLCC), 100nF, ±10%, 100V, X7R, ±10%, SMD 1206; Manufacturer: TDK; Manufacturer Part Number: CGA5L2X7R2A104KT0Y0U
footprint CAP-1206 (1206 (3216M) Capacitor)
pins: 1, 2

## CGA5L2X7R2A105KT0Y0U
designator C?  Capacitance: 1uF  (hidden comment: *)
Capacitor, Ceramic (MLCC), 1uF, ±10%, 100V, X7R, ±10%, SMD 1206; Manufacturer: TDK; Manufacturer Part Number: CGA5L2X7R2A105KT0Y0U
footprint CAP-1206 (1206 (3216M) Capacitor)
pins: 1, 2

## CGA5L2X7R2A474KT0Y0U
designator C?  Capacitance: 470nF  (hidden comment: *)
Capacitor, Ceramic (MLCC), 470nF, ±10%, 100V, X7R, ±10%, SMD 1206; Manufacturer: TDK; Manufacturer Part Number: CGA5L2X7R2A474KT0Y0U
footprint CAP-1206 (1206 (3216M) Capacitor)
pins: 1, 2

## CGA5L3X5R1H106KT0Y0N
designator C?  Capacitance: 10uF  (hidden comment: *)
Capacitor, Ceramic (MLCC), 10uF, ±10%, 50V, X5R, ±10%, SMD 1206; Manufacturer: TDK; Manufacturer Part Number: CGA5L3X5R1H106KT0Y0N
footprint CAP-1206 (1206 (3216M) Capacitor)
pins: 1, 2

## CGA5L3X7R1H105KT0Y0N
designator C?  Capacitance: 1uF  (hidden comment: *)
Capacitor, Ceramic (MLCC), 1uF, ±10%, 50V, X7R, ±10%, SMD 1206; Manufacturer: TDK; Manufacturer Part Number: CGA5L3X7R1H105KT0Y0N
footprint CAP-1206 (1206 (3216M) Capacitor)
pins: 1, 2

## CGA5L3X7R1H105KT0Y0S
designator C?  Capacitance: 1uF  (hidden comment: *)
Capacitor, Ceramic (MLCC), 1uF, ±10%, 50V, X7R, ±10%, SMD 1206; Manufacturer: TDK; Manufacturer Part Number: CGA5L3X7R1H105KT0Y0S
footprint CAP-1206 (1206 (3216M) Capacitor)
pins: 1, 2

## CGA5L3X7R1H225KT0Y0N
designator C?  Capacitance: 2.2uF  (hidden comment: *)
Capacitor, Ceramic (MLCC), 2.2uF, ±10%, 50V, X7R, ±10%, SMD 1206; Manufacturer: TDK; Manufacturer Part Number: CGA5L3X7R1H225KT0Y0N
footprint CAP-1206 (1206 (3216M) Capacitor)
pins: 1, 2

## CGA5L3X7R1H225KT0Y0S
designator C?  Capacitance: 2.2uF  (hidden comment: *)
Capacitor, Ceramic (MLCC), 2.2uF, ±10%, 50V, X7R, ±10%, SMD 1206; Manufacturer: TDK; Manufacturer Part Number: CGA5L3X7R1H225KT0Y0S
footprint CAP-1206 (1206 (3216M) Capacitor)
pins: 1, 2

## CGA5L3X7R1H475KT000N
designator C?  Capacitance: 4.7uF  (hidden comment: *)
Capacitor, Ceramic (MLCC), 4.7uF, ±10%, 50V, X7R, ±10%, SMD 1206; Manufacturer: TDK; Manufacturer Part Number: CGA5L3X7R1H475KT000N
footprint CAP-1206 (1206 (3216M) Capacitor)
pins: 1, 2

## CGA5L3X7R2E104KT0Y0U
designator C?  Capacitance: 100nF  (hidden comment: *)
Capacitor, Ceramic (MLCC), 100nF, ±10%, 250V, X7R, ±10%, SMD 1206; Manufacturer: TDK; Manufacturer Part Number: CGA5L3X7R2E104KT0Y0U
footprint CAP-1206 (1206 (3216M) Capacitor)
pins: 1, 2

## CGA5L3X7S2A225KT0Y0N
designator C?  Capacitance: 2.2uF  (hidden comment: *)
Capacitor, Ceramic (MLCC), 2.2uF, ±10%, 100V, X7S, ±10%, SMD 1206; Manufacturer: TDK; Manufacturer Part Number: CGA5L3X7S2A225KT0Y0N
footprint CAP-1206 (1206 (3216M) Capacitor)
pins: 1, 2

## CGA5L4C0G2J103JT0Y0N
designator C?  Capacitance: 10nF  (hidden comment: *)
Capacitor, Ceramic (MLCC), 10nF, ±5%, 630V, C0G, ±5%, SMD 1206; Manufacturer: TDK; Manufacturer Part Number: CGA5L4C0G2J103JT0Y0N
footprint CAP-1206 (1206 (3216M) Capacitor)
pins: 1, 2

## CGA5L4X7R2J333KT0Y0U
designator C?  Capacitance: 33nF  (hidden comment: *)
Capacitor, Ceramic (MLCC), 33nF, ±10%, 630V, X7R, ±10%, SMD 1206; Manufacturer: TDK; Manufacturer Part Number: CGA5L4X7R2J333KT0Y0U
footprint CAP-1206 (1206 (3216M) Capacitor)
pins: 1, 2

## CGA5L4X7T2W104KT0Y0N
designator C?  Capacitance: 100nF  (hidden comment: *)
Capacitor, Ceramic (MLCC), 100nF, ±10%, 450V, X7T, ±10%, SMD 1206; Manufacturer: TDK; Manufacturer Part Number: CGA5L4X7T2W104KT0Y0N
footprint CAP-1206 (1206 (3216M) Capacitor)
pins: 1, 2

## CL31A105KB9LNNC
designator C?  Capacitance: 1uF  (hidden comment: *)
Capacitor, Ceramic (MLCC), 1uF, ±10%, 50V, X5R, ±10%, SMD 1206; Manufacturer: Samsung Electro-Mechanics; Manufacturer Part Number: CL31A105KB9LNNC
footprint CAP-1206 (1206 (3216M) Capacitor)
pins: 1, 2

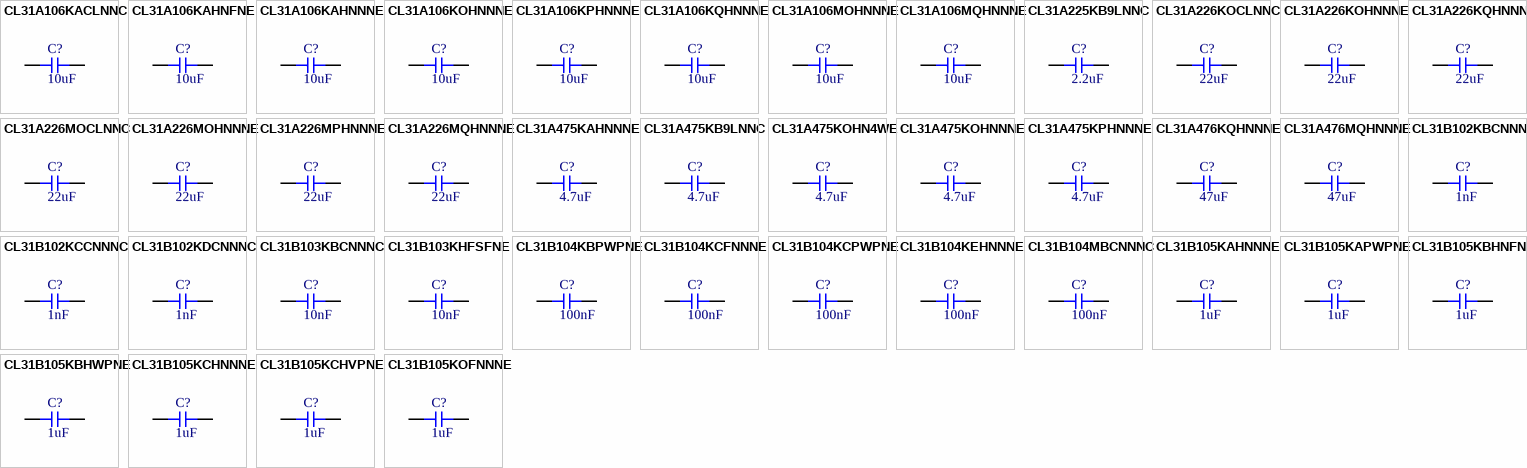
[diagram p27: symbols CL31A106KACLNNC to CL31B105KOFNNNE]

## CL31A106KACLNNC
designator C?  Capacitance: 10uF  (hidden comment: *)
Capacitor, Ceramic (MLCC), 10uF, ±10%, 25V, X5R, ±10%, SMD 1206; Manufacturer: Samsung Electro-Mechanics; Manufacturer Part Number: CL31A106KACLNNC
footprint CAP-1206 (1206 (3216M) Capacitor)
pins: 1, 2

## CL31A106KAHNFNE
designator C?  Capacitance: 10uF  (hidden comment: *)
Capacitor, Ceramic (MLCC), 10uF, ±10%, 25V, X5R, ±10%, SMD 1206; Manufacturer: Samsung Electro-Mechanics; Manufacturer Part Number: CL31A106KAHNFNE
footprint CAP-1206 (1206 (3216M) Capacitor)
pins: 1, 2

## CL31A106KAHNNNE
designator C?  Capacitance: 10uF  (hidden comment: *)
Capacitor, Ceramic (MLCC), 10uF, ±10%, 25V, X5R, ±10%, SMD 1206; Manufacturer: Samsung Electro-Mechanics; Manufacturer Part Number: CL31A106KAHNNNE
footprint CAP-1206 (1206 (3216M) Capacitor)
pins: 1, 2

## CL31A106KOHNNNE
designator C?  Capacitance: 10uF  (hidden comment: *)
Capacitor, Ceramic (MLCC), 10uF, ±10%, 16V, X5R, ±10%, SMD 1206; Manufacturer: Samsung Electro-Mechanics; Manufacturer Part Number: CL31A106KOHNNNE
footprint CAP-1206 (1206 (3216M) Capacitor)
pins: 1, 2

## CL31A106KPHNNNE
designator C?  Capacitance: 10uF  (hidden comment: *)
Capacitor, Ceramic (MLCC), 10uF, ±10%, 10V, X5R, ±10%, SMD 1206; Manufacturer: Samsung Electro-Mechanics; Manufacturer Part Number: CL31A106KPHNNNE
footprint CAP-1206 (1206 (3216M) Capacitor)
pins: 1, 2

## CL31A106KQHNNNE
designator C?  Capacitance: 10uF  (hidden comment: *)
Capacitor, Ceramic (MLCC), 10uF, ±10%, 6.3V, X5R, ±10%, SMD 1206; Manufacturer: Samsung Electro-Mechanics; Manufacturer Part Number: CL31A106KQHNNNE
footprint CAP-1206 (1206 (3216M) Capacitor)
pins: 1, 2

## CL31A106MOHNNNE
designator C?  Capacitance: 10uF  (hidden comment: *)
Capacitor, Ceramic (MLCC), 10uF, ±20%, 16V, X5R, ±20%, SMD 1206; Manufacturer: Samsung Electro-Mechanics; Manufacturer Part Number: CL31A106MOHNNNE
footprint CAP-1206 (1206 (3216M) Capacitor)
pins: 1, 2

## CL31A106MQHNNNE
designator C?  Capacitance: 10uF  (hidden comment: *)
Capacitor, Ceramic (MLCC), 10uF, ±20%, 6.3V, X5R, ±20%, SMD 1206; Manufacturer: Samsung Electro-Mechanics; Manufacturer Part Number: CL31A106MQHNNNE
footprint CAP-1206 (1206 (3216M) Capacitor)
pins: 1, 2

## CL31A225KB9LNNC
designator C?  Capacitance: 2.2uF  (hidden comment: *)
Capacitor, Ceramic (MLCC), 2.2uF, ±10%, 50V, X5R, ±10%, SMD 1206; Manufacturer: Samsung Electro-Mechanics; Manufacturer Part Number: CL31A225KB9LNNC
footprint CAP-1206 (1206 (3216M) Capacitor)
pins: 1, 2

## CL31A226KOCLNNC
designator C?  Capacitance: 22uF  (hidden comment: *)
Capacitor, Ceramic (MLCC), 22uF, ±10%, 16V, X5R, ±10%, SMD 1206; Manufacturer: Samsung Electro-Mechanics; Manufacturer Part Number: CL31A226KOCLNNC
footprint CAP-1206 (1206 (3216M) Capacitor)
pins: 1, 2

## CL31A226KOHNNNE
designator C?  Capacitance: 22uF  (hidden comment: *)
Capacitor, Ceramic (MLCC), 22uF, ±10%, 16V, X5R, ±10%, SMD 1206; Manufacturer: Samsung Electro-Mechanics; Manufacturer Part Number: CL31A226KOHNNNE
footprint CAP-1206 (1206 (3216M) Capacitor)
pins: 1, 2

## CL31A226KQHNNNE
designator C?  Capacitance: 22uF  (hidden comment: *)
Capacitor, Ceramic (MLCC), 22uF, ±10%, 6.3V, X5R, ±10%, SMD 1206; Manufacturer: Samsung Electro-Mechanics; Manufacturer Part Number: CL31A226KQHNNNE
footprint CAP-1206 (1206 (3216M) Capacitor)
pins: 1, 2

## CL31A226MOCLNNC
designator C?  Capacitance: 22uF  (hidden comment: *)
Capacitor, Ceramic (MLCC), 22uF, ±20%, 16V, X5R, ±20%, SMD 1206; Manufacturer: Samsung Electro-Mechanics; Manufacturer Part Number: CL31A226MOCLNNC
footprint CAP-1206 (1206 (3216M) Capacitor)
pins: 1, 2

## CL31A226MOHNNNE
designator C?  Capacitance: 22uF  (hidden comment: *)
Capacitor, Ceramic (MLCC), 22uF, ±20%, 16V, X5R, ±20%, SMD 1206; Manufacturer: Samsung Electro-Mechanics; Manufacturer Part Number: CL31A226MOHNNNE
footprint CAP-1206 (1206 (3216M) Capacitor)
pins: 1, 2

## CL31A226MPHNNNE
designator C?  Capacitance: 22uF  (hidden comment: *)
Capacitor, Ceramic (MLCC), 22uF, ±20%, 10V, X5R, ±20%, SMD 1206; Manufacturer: Samsung Electro-Mechanics; Manufacturer Part Number: CL31A226MPHNNNE
footprint CAP-1206 (1206 (3216M) Capacitor)
pins: 1, 2

## CL31A226MQHNNNE
designator C?  Capacitance: 22uF  (hidden comment: *)
Capacitor, Ceramic (MLCC), 22uF, ±20%, 6.3V, X5R, ±20%, SMD 1206; Manufacturer: Samsung Electro-Mechanics; Manufacturer Part Number: CL31A226MQHNNNE
footprint CAP-1206 (1206 (3216M) Capacitor)
pins: 1, 2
